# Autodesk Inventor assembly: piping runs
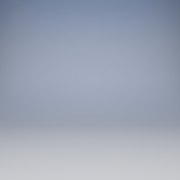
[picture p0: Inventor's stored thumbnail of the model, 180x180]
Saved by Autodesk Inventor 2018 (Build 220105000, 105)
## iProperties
Created: 2006-09
Part Number: piping runs
Document SubType Name: Tube & Pipe
Manufacturer: Standard
Standards Organization: Custom
Material: Ogólny
ActiveState: False
BendRadius: UnInitValue
CouplingKey: UnInitValue
DefaultBendRadius: UnInitValue
Diameter: 6
DiameterType: Nominal
Elbow90Key: v3#6a678020-d9d9-4685-bba9-906b9a167083#10
ElbowCustomKey: UnInitValue
EndFittingKey: UnInitValue
Ending: UnInitValue
FittingMaterial: UnInitValue
FittingStandard: UnInitValue
FlangeKey: v3#24991861-26e3-4c21-a713-f46e314eddd5#10
Gap: 2,388 mm
GasketKey: v3#2a41914c-f5fb-4682-9c6a-1870d826d3d0#23
ID: UnInitValue
IntermediateSegmentsInc: 0.00001 in
IntermediateSegmentsMax: 5080,000 mm
IntermediateSegmentsMin: 76,200 mm
IsButtWelded: True
IsFlanged: True
IsSelfDraining: False
Material: UnInitValue
MixedUnits: False
Name: ASTM A 53/A 53M - Rura stalowa kołnierzowa/spawana doczołowo
OD: UnInitValue
PipeKey: v3#4ce5e9fa-6da0-4801-ac02-ee7a0fb518d6#77
PipeType: Rigid Pipe
PipingComponentColor: As Material
RoundUpValue: UnInitValue
RouteDirection45: False
RouteDirection90: True
Schedule: 40
ShowGap: True
Standard: UnInitValue
StartFittingKey: UnInitValue
SuppressEndFitting: UnInitValue
SuppressStartFitting: UnInitValue
TerminationSegmentsInc: 0.00001 in
TerminationSegmentsMax: 5080,000 mm
TerminationSegmentsMin: 76,200 mm
UseFlangsForCouplings: False
UseSubASM: UnInitValue
_ComponentInfo: <CS><C N="Pipe" R="8.413750" OR="8.413750" IR="7.702550" PL="PL" PartType="pipe" SymKey="" PN="ASTM A 53/A 53M Pipe 6 - Schedule 40"><CO N="1"><FE V="2"/><FD V=
CouplingKey: v3#d2599e7a-1865-48da-a234-5418a1cd5dfe#3
Diameter: 1/2
Elbow45Key: v3#6ce5b1be-37aa-4928-b23a-0df64e6ddf38#2
Elbow90Key: v3#9fba244e-81ed-4fc6-a9ac-7eb372fa3ffe#3
FlangeKey: UnInitValue
Gap: UnInitValue
GasketKey: UnInitValue
IntermediateSegmentsInc: 2,540 mm
IntermediateSegmentsMin: 50,800 mm
IsButtWelded: False
IsFlanged: False
Name: DIN 2458/DIN EN 10242 - Rury stalowe gwintowane i stalowe łączniki
PipeKey: v3#d689fd5f-ac5a-46d7-a883-3089b2f6e0a4#28
RouteDirection45: True
Schedule: ID=12.3
ShowGap: UnInitValue
TerminationSegmentsInc: 2,540 mm
TerminationSegmentsMin: 50,800 mm
UseFlangsForCouplings: UnInitValue
_ComponentInfo: <CS><C N="Pipe" R="1.065000" IR="0.615000" PL="PL" PN="DIN 2458 Pipe with Threaded Ends 21.3 x 4.5"><CO N="1"><FE V="0"/><FD V="1"/><ET V="Threaded"/><NS V="1/2
Angle: UnInitValue
BendRadius: 12,700 mm
Elbow45Key: UnInitValue
Elbow90Key: UnInitValue
EndFittingKey: v3#cc3bd835-95a2-497d-9893-176cd9c426f6#7
ID: 1,27
IntermediateSegmentsInc: UnInitValue
IntermediateSegmentsMax: UnInitValue
IntermediateSegmentsMin: UnInitValue
IsButtWelded: UnInitValue
IsFlanged: UnInitValue
IsSelfDraining: UnInitValue
MixedUnits: UnInitValue
Name: Przewód hydrauliczny – gwint stożkowy wewnętrzny
OD: 2,2352
PipeKey: v3#d489867e-ac9b-47ea-b952-0a1b885f66be#4
PipeType: Flexible Hose
RoundUpValue: 3,175 mm
RouteDirection45: UnInitValue
RouteDirection90: UnInitValue
Schedule: ID=0.5
StartFittingKey: v3#cc3bd835-95a2-497d-9893-176cd9c426f6#7
SuppressEndFitting: False
SuppressStartFitting: False
TerminationSegmentsInc: UnInitValue
TerminationSegmentsMax: UnInitValue
TerminationSegmentsMin: UnInitValue
UseSubASM: True
_ComponentInfo: <CS><C N="Pipe" R="1.117600" OR="1.117600" IR="0.635000" PL="PL" PartType="" SymKey="" PN="Parker Hydraulic Hose - No Skive 1/2"><CO N="1"><FE V="0"/><FD V="0"/
Diameter: M40
Elbow45Key: v3#81684a3f-f2a4-4fe6-95b1-f067ddead22f#1
Elbow90Key: v3#451ae64e-c79d-4cba-b533-c09b8090ecb2#1
IntermediateSegmentsInc: 10,000 mm
IntermediateSegmentsMax: 9000,000 mm
IntermediateSegmentsMin: 1000,000 mm
Name: ISO 2531 - Rury żelazne kołnierzowe i łączniki
PipeKey: v3#f52fbdcb-ece8-4303-8b76-5dbe8c7f2f9c#16
Schedule: PN10
TerminationSegmentsInc: 10,000 mm
TerminationSegmentsMax: 9000,000 mm
TerminationSegmentsMin: 1000,000 mm
_ComponentInfo: <CS><C N="Pipe" R="2.700000" IR="2.000000" PL="PL" PN="ISO 2531 Pipe with Integrally Cast Flanges DN40 PN 10"><CO N="1"><FE V="0"/><FD V="0"/><ET V="Flanged"/><
EndFittingKey: v3#c8250148-a7b6-458b-b7bd-3b56763ca7cc#13
Name: Przewód hydrauliczny – gwint stożkowy zewnętrzny
StartFittingKey: v3#c8250148-a7b6-458b-b7bd-3b56763ca7cc#13
Elbow90Key: v3#97ecdcaf-8aa3-4fb0-8b6a-3da783de2ad5#108
Gap: 1,575 mm
Name: ASTM A 53/A-ASME B16.9 - Rura stalowa ze szwem
_ComponentInfo: <CS><C N="Elbow90" ER="15.240000" S1="15.240000" S2="15.240000" D1="0.000000" D2="0.000000" PartType="fitting" SymKey="ELBW"><CO N="1"><FE V="2"/><FD V="0"/><ET
CouplingKey: v3#181262db-c004-4877-bc40-c64b931a44f6#3
Elbow45Key: v3#960407aa-00b9-4d72-aae7-d50595845cfd#3
Elbow90Key: v3#6c92b367-65e9-486b-b952-db434ae2548d#3
IntermediateSegmentsInc: 1,000 mm
IntermediateSegmentsMax: 5000,000 mm
IntermediateSegmentsMin: 20,000 mm
Name: JIS G 3442/JIS B 2301 - Rury stalowe gwintowane ze stalowymi łącznikami
PipeKey: v3#9964fba4-9d5a-4d75-85a8-e38022ccdce1#2
Schedule: ID=16.1
TerminationSegmentsInc: 1,000 mm
TerminationSegmentsMax: 5000,000 mm
TerminationSegmentsMin: 20,000 mm
_ComponentInfo: <CS><C N="Pipe" R="1.085000" IR="0.805000" PL="PL" PN="JIS G 3442 Pipe with Threaded Ends 21.7 x 2.8"><CO N="1"><FE V="0"/><FD V="1"/><ET V="Threaded"/><NS V="1
CouplingKey: v3#771d4942-b9e7-43bc-9d41-ab12a9580492#3
Elbow45Key: v3#626cc28c-1a24-4045-be0d-40d896dc828d#3
Elbow90Key: v3#bc6b44ab-9235-4590-b699-74498030a1ff#3
Name: ANSI/ASME B36.19M-ASME B16.3 - Rury gwintowane ze stalowymi łącznikami
PipeKey: v3#323c0148-c750-449d-a0c6-11721f2a5046#1
Schedule: 40S
_ComponentInfo: <CS><C N="Pipe" R="1.066800" IR="0.789940" PL="PL" PN="ANSI/ASME B36.19M Pipe with Threaded Ends 1/2 - Schedule 40S"><CO N="1"><FE V="0"/><FD V="1"/><ET V="Thre
CouplingKey: v3#b06656e5-2b55-488c-bcf0-6a90c79c4683#2
Elbow45Key: v3#421a8b99-1721-409a-bc3b-c00889561754#1
Elbow90Key: v3#17490b17-1dd8-40fc-8de7-1a70c3bab2d7#1
IntermediateSegmentsMax: 2540,000 mm
IntermediateSegmentsMin: 60,000 mm
Name: ISO 4065-ISO 3633 - Rury i złączki PCV
PipeKey: v3#4f84f716-5ba0-45ef-967a-c32c3d7345ce#70
Schedule: S40
TerminationSegmentsMax: 2540,000 mm
TerminationSegmentsMin: 60,000 mm
_ComponentInfo: <CS><C N="Pipe" R="2.000000" IR="1.950000" PL="PL" PN="ISO 4065 Pipe 40 x 0.5 S40"><CO N="1"><FE V="0"/><FD V="0"/><ET V="Jointed"/><NS V="M40"/><MA V="6.000000
CouplingKey: v3#0dc1ae02-7bbf-4ccf-8498-581434b0a765#3
DefaultBendRadius: 50,800 mm
IntermediateSegmentsMin: 0,000 mm
Name: ASTM B 88-ASME B16.22 - Rury miedziane lutowane
PipeKey: v3#44b182c9-4bce-4825-bb4d-596143122252#7
PipeType: Tubing
Schedule: L
TerminationSegmentsMin: 0,000 mm
_ComponentInfo: <CS><C N="Pipe" R="0.793750" IR="0.692150" PL="PL" PN="ASTM B 88 Tube 1/2 - Type L"><CO N="1"><FE V="0"/><FD V="0"/><ET V="Soldered"/><NS V="1/2"/><MA V="2.5400
EndFittingKey: v3#c5e461f5-5e73-4f2e-8c1e-4358d4d6f46c#4
Name: Przewód hydrauliczny – gwint wewnętrzny - obrotowy
StartFittingKey: v3#c5e461f5-5e73-4f2e-8c1e-4358d4d6f46c#4
CouplingKey: v3#29993622-4c6a-437e-8b8c-43a0846f8735#1
Elbow45Key: v3#d7b5d569-4a12-4d65-ba55-12203d6ac7ed#1
Elbow90Key: v3#25d2a8db-6517-4627-a5a4-9d27e4d26b9b#1
IntermediateSegmentsMin: 25,400 mm
Name: ASTM D 1785-ASTM D 2466 - Rury i złączki PCV
PipeKey: v3#4bf12049-4375-491b-8f13-d4ee0c517c57#1
TerminationSegmentsMin: 25,400 mm
_ComponentInfo: <CS><C N="Pipe" R="1.066800" IR="0.789940" PL="PL" PN="ASTM D 1785 Pipe 1/2 - Schedule 40"><CO N="1"><FE V="0"/><FD V="0"/><ET V="Jointed"/><NS V="1/2"/><MA V="
Name: Przewód hydrauliczny – bez złączek
SuppressEndFitting: True
SuppressStartFitting: True
Name: DIN 8062/DIN 8063 - Rury i złączki PCV-U
RoutePreview: Solid
Schedule: 5
IntermediateSegmentsMin: 60.000 mm
IntermediateSegmentsMax: 5000.000 mm
IntermediateSegmentsInc: 1.000 mm
TerminationSegmentsMin: 60.000 mm
TerminationSegmentsMax: 5000.000 mm
TerminationSegmentsInc: 1.000 mm
SolidRoutePreviewColor: 12632064
PipeKey: v3#3d294dc7-89c3-4c37-a0ae-28c15a73bfd0#13
CouplingKey: v3#3edf83e2-464b-4b31-84c5-c329ffbf2a4f#5
Elbow90Key: v3#fbd68fd5-590c-4cb5-8c20-9e9bdd396a04#5
Elbow45Key: v3#2f597a97-b15b-49d4-87cb-7bfe69eb62ee#5
_ComponentInfo: <CS><C N="Pipe" R="2.000000" IR="1.700000" PL="PL" PN="DIN 8062 Pipe 40 x 3"><CO N="1"><FE V="0"/><FD V="0"/><ET V="Jointed"/><NS V="M40"/><MA V="8.000000"/><MI
FlangeKey: v3#c11442d2-c568-438f-a870-8ac9b5b636cb#10
Name: ASTM A 53/A-ASME B16.5 - Rura stalowa gwintowana kołnierzowa
PipeKey: v3#c5bd7d28-cdb3-4507-9f3d-c2787d93fe8a#40
_ComponentInfo: <CS><C N="Elbow90" ER="21.590000" S1="21.590000" S2="21.590000" D1="0.000000" D2="0.000000" PartType="fitting" SymKey="ELFL"><CO N="1"><FE V="2"/><FD V="1"/><ET
EndFittingKey: v3#b50cb43e-68c0-48ac-8e25-7ef224ce0e6c#3
Name: Przewód hydrauliczny – gwint zewnętrzny prosty
StartFittingKey: v3#b50cb43e-68c0-48ac-8e25-7ef224ce0e6c#3
ActiveState: True
CouplingKey: v3#52ad3977-2b89-4007-a6a6-7626bac0ae85#4
Elbow45Key: v3#5c2ab816-abcb-49a6-a106-4733af000f51#4
Elbow90Key: v3#160eac10-3e6f-4b5c-839c-61eee0d373dc#4
Name: ASME B36.10M-ASME B16.11 - Rury stalowe gwintowane
PipeKey: v3#4a736116-503a-44ad-a922-868ac6b46736#1
Schedule: 30
_ComponentInfo: <CS><C N="Pipe" R="1.066800" IR="0.825500" PL="PL" PN="ASME B36.10M Pipe with Threaded Ends 1/2 - Schedule 30"><CO N="1"><FE V="0"/><FD V="1"/><ET V="Threaded"/
CouplingKey: v3#7e56b2cb-a132-4546-b8a7-a14538454b94#3
Elbow45Key: v3#a96c5204-26e4-4bb2-b8f1-f0623fbc94bb#2
Elbow90Key: v3#b72bb08b-ad33-47cc-a03d-7f3d76c6616b#3
Name: ISO 7598/ISO 49 - Rury stalowe gwintowane ze stalowymi łącznikami
PipeKey: v3#1052637f-74b5-47f4-adeb-d4e8d3fa53b8#1
_ComponentInfo: <CS><C N="Pipe" R="1.065000" IR="0.805000" PL="PL" PN="ISO 7598 Tube with Threaded Ends DN15"><CO N="1"><FE V="0"/><FD V="1"/><ET V="Threaded"/><NS V="1/2"/><MA
Elbow45Key: v3#97879d80-057e-491b-840b-74a9b3a7cf63#17
Elbow90Key: v3#ace818b0-7b7c-4ad9-b19c-6da358a202c1#17
Name: DIN 2458/DIN 2605 - Rury stalowe spawane i łączniki
PipeKey: v3#dcef2839-8903-4c98-a96c-b861f5d9bb7f#98
Schedule: ID=30.7
_ComponentInfo: <CS><C N="Pipe" R="2.415000" IR="1.535000" PL="PL" PN="DIN 2458 Pipe 48.3 x 8.8"><CO N="1"><FE V="2"/><FD V="0"/><ET V="Welded"/><NS V="M40"/><MA V="0.000000"/>
CouplingKey: v3#eaa8de87-dc67-4eca-ba7e-4267a30f8f7f#2
Elbow45Key: v3#2769403e-a4fd-4a4c-8e4c-659ea845bd78#2
Elbow90Key: v3#c4513a61-3106-4a78-baf9-a1badd100245#2
IntermediateSegmentsMax: 2500,000 mm
Name: JIS K 6741/JIS K 6739 - Rury i złączki PCV-U
PipeKey: v3#45338dd0-af69-48c0-a2ed-8ade33a08701#5
Schedule: VP
TerminationSegmentsMax: 2500,000 mm
_ComponentInfo: <CS><C N="Pipe" R="2.400000" IR="2.040000" PL="PL" PN="JIS K 6741 Pipe VP 40"><CO N="1"><FE V="0"/><FD V="1"/><ET V="Jointed"/><NS V="M40"/><MA V="4.000000"/><M
Angle: 92,00 deg
Diameter: 1
Elbow45Key: v3#bf26aa2a-f3dd-474c-8758-922a145c2b02#15
Elbow90Key: v3#3e93288f-9bb7-4e46-9d6b-544f8c20ca1c#3
ElbowCustomKey: v3#1f3bd44a-47ab-42f9-b3e0-74afa0c3f0ca#3
IsSelfDraining: True
Name: ASME BPE - Rura stalowa kołnierzowa
PipeKey: v3#b10c956f-6fc6-429e-8056-0864a8581764#35
Schedule: ID=0.87
_ComponentInfo: <CS><C N="Pipe" R="1.270000" OR="1.270000" IR="1.104900" PL="PL" PartType="pipe" SymKey="" PN="ASTM A 269 Tube with Welded ends 1 x 0.87"><CO N="1"><FE V="2"/><
CouplingKey: v3#ed415c76-4cec-44a3-ba67-72e47bf70384#4
Elbow45Key: v3#2e5fd082-3851-4eb0-bde1-6c7078a7d72b#4
Elbow90Key: v3#82a08401-12d7-413b-b7f9-9cf3b607be7b#4
Name: ASTM A53/A53M-ASME B16.11 - Rury stalowe spawane
PipeKey: v3#4ce5e9fa-6da0-4801-ac02-ee7a0fb518d6#7
_ComponentInfo: <CS><C N="Pipe" R="1.066800" IR="0.789940" PL="PL" PN="ASTM A 53/A 53M Pipe 1/2 - Schedule 40"><CO N="1"><FE V="0"/><FD V="0"/><ET V="Welded"/><NS V="1/2"/><MA 
EndFittingKey: v3#933069c9-73b6-4141-af99-628d4a97b2c2#1
Name: Przewód hydrauliczny – złączki kołnierzowe SAE
StartFittingKey: v3#933069c9-73b6-4141-af99-628d4a97b2c2#1
CouplingKey: v3#12b64993-10e6-4915-8315-0c0cce209ad0#8
Elbow45Key: v3#28e76e79-e22c-40ab-8be2-ff545b1407c5#8
Elbow90Key: v3#1f65ece3-c41a-48d4-8661-909ed34ade86#8
Name: JIS G 3458/JIS B 2316 - Rury stalowe spawane i łączniki
PipeKey: v3#da14b0ab-0b36-4851-8d66-8c9cd0bcbe86#23
Schedule: 80
_ComponentInfo: <CS><C N="Pipe" R="2.430000" IR="1.920000" PL="PL" PN="JIS G 3458 Pipe 40 A x Sch 80"><CO N="1"><FE V="0"/><FD V="1"/><ET V="Welded"/><NS V="M40"/><MA V="0.0000
count: 52
Refkey_Axis1_Context: 2|0|0|0|1|0|0|0|
Refkey_Axis1: 6|0|0|0|44|0|0|0|78|0|65|0|77|0|69|0|83|0|10|0|67|0|111|0|108|0|111|0|114|0|115|0|10|0|49|0|58|0|10|0|10|0|69|0|78|0|68|0|10|0|0|0|
Refkey_Axis2_Context: 2|0|0|0|1|0|0|0|
Refkey_Axis2: 6|0|0|0|88|0|0|0|78|0|65|0|77|0|69|0|83|0|10|0|67|0|111|0|108|0|111|0|114|0|115|0|10|0|49|0|58|0|82|0|111|0|117|0|116|0|101|0|32|0|85|0|73|0|32|0|84|0|111|0|111
Refkey_Axis3_Context: 2|0|0|0|1|0|0|0|
Refkey_Axis3: 6|0|0|0|88|0|0|0|78|0|65|0|77|0|69|0|83|0|10|0|67|0|111|0|108|0|111|0|114|0|115|0|10|0|49|0|58|0|82|0|111|0|117|0|116|0|101|0|32|0|85|0|73|0|32|0|84|0|111|0|111
Refkey_Ext_Context: 2|0|0|0|1|0|0|0|
Refkey_Ext: 6|0|0|0|92|0|0|0|78|0|65|0|77|0|69|0|83|0|10|0|67|0|111|0|108|0|111|0|114|0|115|0|10|0|49|0|58|0|82|0|111|0|117|0|116|0|101|0|32|0|85|0|73|0|32|0|84|0|111|0|111
Refkey_Snap_Context: 2|0|0|0|1|0|0|0|
Refkey_Snap: 6|0|0|0|84|0|0|0|78|0|65|0|77|0|69|0|83|0|10|0|67|0|111|0|108|0|111|0|114|0|115|0|10|0|49|0|58|0|82|0|111|0|117|0|116|0|101|0|32|0|85|0|73|0|32|0|84|0|111|0|111
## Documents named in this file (1)
- C:\Users\Joffi\Desktop\Templates.Base\Tube & Pipe\piping runs.iam
